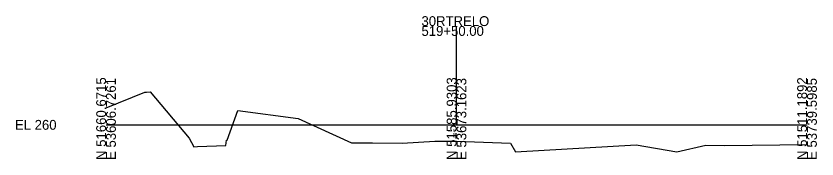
# Model space of a CAD drawing. Extents: x 12366 to 12594, y 96215 to 100251.
# Drawn here: x 12365.6 to 12594.1, y 97714.9 to 97755.6 of the extents above; entities that cross this region are included whole.
import ezdxf

# ---------------------------------------------------------------- set-up
doc = ezdxf.new("R2010")
doc.units = 0
for name, color, linetype in [('Level 10', 7, 'Continuous'), ('Level 60', 7, 'Continuous'), ('Level 63', 7, 'Continuous')]:
    doc.layers.add(name, color=color, linetype=linetype)

msp = doc.modelspace()

# ---------------------------------------------------------------- linework, layer by layer
at = {"layer": 'Level 60'}
for p, q in [((12391.3, 97729.51), (12402.35, 97733.92)), ((12402.35, 97733.92), (12402.8, 97733.98)), ((12402.8, 97733.98), (12403.89, 97734)), ((12403.89, 97734), (12415.05, 97720.83)), ((12425.82, 97720.32), (12428.91, 97728.72)), ((12428.91, 97728.72), (12446.07, 97726.44)), ((12446.07, 97726.44), (12461.3, 97719.55)), ((12415.05, 97720.83), (12416.3, 97718.4)), ((12425.43, 97718.77), (12425.67, 97720.32)), ((12425.67, 97720.32), (12425.82, 97720.32)), ((12416.3, 97718.4), (12417.4, 97718.47)), ((12417.4, 97718.47), (12425.43, 97718.77)), ((12461.3, 97719.55), (12467.33, 97719.55)), ((12467.33, 97719.55), (12475.8, 97719.43)), ((12475.8, 97719.43), (12485.14, 97719.95)), ((12485.14, 97719.95), (12491.3, 97719.96)), ((12491.3, 97719.96), (12506.69, 97719.46)), ((12506.69, 97719.46), (12508.16, 97716.95)), ((12508.16, 97716.95), (12542.59, 97718.91)), ((12542.59, 97718.91), (12554.14, 97716.98)), ((12554.14, 97716.98), (12562.4, 97718.85)), ((12562.4, 97718.85), (12567.86, 97718.79)), ((12567.86, 97718.79), (12591.3, 97719.09))]:
    msp.add_line(p, q, dxfattribs=at)
at = {"layer": 'Level 63'}
for p, q in [((12491.3, 97724.64), (12491.3, 97752.74)), ((12391.3, 97724.64), (12491.3, 97724.64)), ((12491.3, 97724.64), (12591.3, 97724.64))]:
    msp.add_line(p, q, dxfattribs=at)

# ---------------------------------------------------------------- texts
at = {"layer": 'Level 10'}
msp.add_text('255.32', height=0.6, rotation=90, dxfattribs=at).set_placement((12490.9, 97720.96))
at = {"layer": 'Level 63'}
for s, p in [('30RTRELO', (12481.3, 97752.74)), ('519+50.00', (12481.3, 97749.94)), ('EL 260', (12365.31, 97723.24))]:
    msp.add_text(s, height=2.8, dxfattribs=at).set_placement(p)
for s, p in [('N 51660.6715', (12391.3, 97714.64)), ('E 53606.7261', (12394.1, 97714.64)), ('N 51585.9303', (12491.3, 97714.64)), ('E 53673.1623', (12494.1, 97714.64)), ('N 51511.1892', (12591.3, 97714.64)), ('E 53739.5985', (12594.1, 97714.64))]:
    msp.add_text(s, height=2.8, rotation=90, dxfattribs=at).set_placement(p)

doc.saveas('drawing.dxf')
